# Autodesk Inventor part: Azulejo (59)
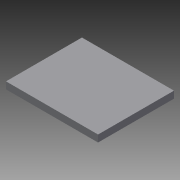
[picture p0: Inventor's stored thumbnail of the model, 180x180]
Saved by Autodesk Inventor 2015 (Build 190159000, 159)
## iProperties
Created: 2015-04
Part Number: Azulejo (59)
Material: Genérico
Document SubType Name: Modeling
Designer: Felipe
Density: 1 g/cm^3
Appearance: Padrão
Author: Felipe
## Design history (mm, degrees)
sketch "Sketch1"
  geometry: L1 (7081.362, 848.164)-(5601.362, 848.164); L2 (5581.362, 848.164)-(4101.362, 848.164); L3 (4081.362, 848.164)-(2601.362, 848.164); L4 (2581.362, 728.164)-(125.504, 728.164); L5 (7101.362, 848.164)-(7101.362, 908.164); L6 (5601.362, 848.164)-(5601.362, 908.164); L7 (5601.362, 908.164)-(7081.362, 908.164); L8 (4101.362, 848.164)-(4101.362, 908.164); L9 (4101.362, 908.164)-(5581.362, 908.164); L10 (5581.362, 908.164)-(5581.362, 848.164); L11 (2601.362, 848.164)-(2601.362, 908.164); L12 (2601.362, 908.164)-(4081.362, 908.164); L13 (4081.362, 908.164)-(4081.362, 848.164); L14 (7081.362, 908.164)-(7081.362, 848.164); L15 (1101.362, 728.164)-(1101.362, 788.164); L16 (1101.362, 788.164)-(2581.362, 788.164); L17 (2581.362, 788.164)-(2581.362, 728.164); L18 (925.504, 728.164)-(925.504, 708.268); L19 (115.504, 828.363)-(115.504, 88.164); L20 (125.504, 828.363)-(125.504, 88.164); L21 (925.504, -31.836)-(925.504, 768.164); L22 (7101.362, 888.164)-(7101.362, 848.164); L23 (5601.362, 168.164)-(5601.362, 908.164); L24 (5601.362, 908.164)-(7081.362, 908.164); L25 (7081.362, 888.164)-(7081.362, 848.164); L26 (5581.362, 908.164)-(5181.362, 908.164); L27 (5581.362, 88.164)-(5581.362, 888.164); L28 (4101.362, 908.164)-(5101.362, 908.164); L29 (4101.362, 88.164)-(4101.362, 888.164); L30 (4081.362, 88.164)-(4081.362, 888.164); L31 (4081.362, 908.164)-(2601.362, 908.164); L32 (2601.362, 888.164)-(2601.362, 88.164); L33 (2581.362, -31.836)-(2581.362, 768.164); L34 (2581.362, 788.164)-(1101.362, 788.164); L35 (1101.362, 768.164)-(1101.362, -31.836); L36 (1081.362, 908.164)-(681.362, 908.164); L37 (425.504, 88.164)-(425.504, 68.164); L38 (425.504, 68.164)-(925.504, 68.164); L39 (1601.362, 88.164)-(1601.362, 68.164); L40 (1601.362, 68.164)-(1101.362, 68.164); L41 (3601.362, 88.164)-(3601.362, 68.164); L42 (3601.362, 68.164)-(2601.362, 68.164); L43 (5161.362, 88.164)-(5161.362, 848.164); L44 (5161.362, 848.164)-(5581.362, 848.164); L45 (5581.362, 848.164)-(5581.362, 88.164); L46 (5581.362, 88.164)-(5161.362, 88.164); L47 (5161.362, 88.164)-(5161.362, 848.164); L48 (925.504, 68.164)-(125.504, 68.164); L49 (125.504, 68.164)-(125.504, 728.164); L50 (925.504, 728.164)-(925.504, 68.164); L51 (5161.362, 88.164)-(4101.362, 88.164); L52 (4101.362, 88.164)-(4101.362, 848.164); L53 (4101.362, 848.164)-(5161.362, 848.164); L54 (5161.362, 848.164)-(5161.362, 88.164); L55 (925.504, 68.164)-(125.504, 68.164); L56 (125.504, 68.164)-(125.504, 728.164); L57 (125.504, 728.164)-(925.504, 728.164); L58 (925.504, 728.164)-(925.504, 68.164); 1 further point
  constraints: 116 end point, 21 point on line, 7 parallel, 4 horizontal, 4 perpendicular
  dimensions: "d2" = 125.50386 distance from line of L20 point (0, 0); "d3" = 68.16406 distance from line of L48 point (0, 0); "d4" = 660 distance between parallel lines of L4 L48; "d5" = 800 distance between parallel lines of L20 L21
extrude "Extrusion1" new body sketch "Sketch1" distance "d0" = 60; taper "d1" = 0 deg
body "Solid1"
